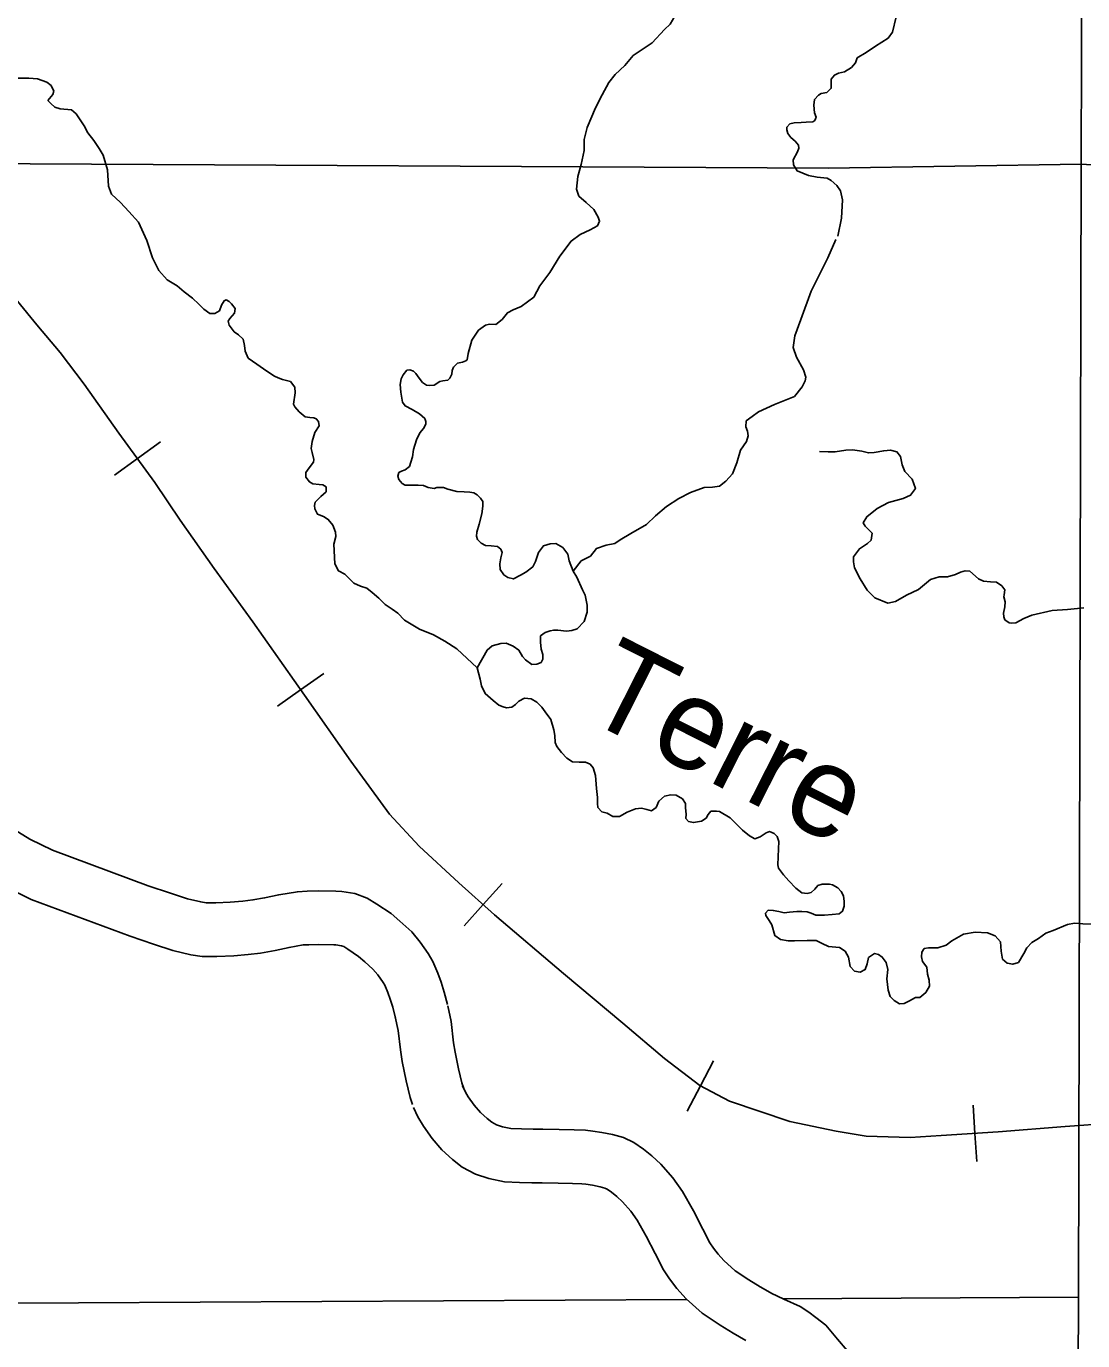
# Model space of a CAD drawing. Extents: x 8749 to 11879, y 13275 to 15339.
# Drawn here: x 10219.7 to 10318.2, y 14295 to 14417.5 of the extents above; entities that cross this region are included whole.
import ezdxf

# ---------------------------------------------------------------- set-up
doc = ezdxf.new("R2010")
doc.units = 0
for name, color, linetype in [('Level 10', 7, 'Continuous'), ('Level 31', 7, 'Continuous'), ('Level 35', 7, 'Continuous'), ('Level 4', 7, 'Continuous'), ('Level 40', 7, 'Continuous'), ('Level 5', 7, 'Continuous')]:
    doc.layers.add(name, color=color, linetype=linetype)

msp = doc.modelspace()

# ---------------------------------------------------------------- linework, layer by layer
at = {"layer": 'Level 10'}
for points in [[(10258.95, 14326.33), (10258.65, 14327.48), (10258.35, 14328.41), (10258.06, 14329.25), (10257.59, 14330.35), (10257.16, 14331.1), (10256.41, 14332.15), (10255.62, 14333.12), (10254.51, 14334.1), (10253.68, 14334.81), (10252.37, 14335.69), (10251.46, 14336.26), (10250.3, 14336.67), (10249.08, 14336.86), (10248.54, 14336.89), (10246.89, 14336.92), (10245.85, 14336.9), (10244.95, 14336.85), (10243.21, 14336.56), (10241.89, 14336.27), (10240.8, 14336.08), (10239.85, 14335.97), (10238.69, 14335.87), (10237.34, 14335.81), (10236.45, 14335.82), (10235.94, 14335.89), (10234.71, 14336.18), (10233.11, 14336.71), (10231.02, 14337.41), (10222.1, 14340.72), (10220.01, 14341.74), (10218.54, 14342.64)], [(10217.6, 14337.35), (10220.12, 14336.12), (10229.36, 14332.69), (10231.53, 14331.96), (10233.34, 14331.37), (10235.02, 14330.97), (10236.07, 14330.82), (10237.43, 14330.8), (10239.02, 14330.88), (10240.35, 14330.99), (10241.52, 14331.12), (10242.87, 14331.36), (10244.17, 14331.65), (10245.5, 14331.88), (10246.03, 14331.91), (10246.89, 14331.92), (10248.35, 14331.89), (10248.55, 14331.88), (10249.07, 14331.8), (10249.28, 14331.73), (10249.65, 14331.49), (10250.65, 14330.82), (10251.23, 14330.32), (10252, 14329.64), (10252.44, 14329.11), (10252.95, 14328.39), (10253.11, 14328.12), (10253.39, 14327.46), (10253.61, 14326.82), (10253.84, 14326.09), (10254.11, 14325.07)], [(10260.47, 14318.49), (10260.3, 14319.03), (10259.97, 14320.33), (10259.66, 14321.88), (10259.52, 14322.77), (10259.29, 14324.74), (10258.97, 14326.22)], [(10254.08, 14325.18), (10254.35, 14323.92), (10254.57, 14322.11), (10254.73, 14321.02), (10255.09, 14319.22), (10255.48, 14317.67), (10255.69, 14317.01)], [(10289.27, 14299.36), (10288.12, 14300.02), (10287.05, 14300.66), (10285.79, 14301.51), (10284.72, 14302.47), (10284.18, 14303.05), (10283.76, 14303.62), (10283.43, 14304.12), (10282.77, 14305.4), (10281.89, 14307.1), (10280.88, 14308.91), (10279.96, 14310.18), (10278.86, 14311.44), (10278.02, 14312.21), (10277.24, 14312.85), (10276.34, 14313.47), (10275.36, 14313.92), (10274.35, 14314.21), (10273.33, 14314.41), (10272.51, 14314.53), (10271.83, 14314.61), (10270.75, 14314.64), (10269.36, 14314.68), (10267.83, 14314.7), (10266.95, 14314.71), (10265.85, 14314.75), (10264.84, 14314.78), (10264.07, 14314.94), (10263.52, 14315.12), (10263.08, 14315.35), (10262.66, 14315.69), (10262.03, 14316.27), (10261.45, 14316.95), (10260.89, 14317.72), (10260.63, 14318.16), (10260.36, 14318.76)], [(10255.79, 14316.73), (10256.18, 14315.86), (10256.7, 14314.98), (10257.51, 14313.85), (10258.43, 14312.79), (10259.4, 14311.89), (10260.32, 14311.16), (10261.55, 14310.5), (10262.79, 14310.1), (10264.25, 14309.8), (10265.67, 14309.75), (10266.82, 14309.71), (10267.77, 14309.7), (10269.26, 14309.68), (10270.61, 14309.64), (10271.47, 14309.62), (10271.85, 14309.57), (10272.47, 14309.48), (10273.19, 14309.34), (10273.62, 14309.22), (10273.85, 14309.11), (10274.24, 14308.84), (10274.74, 14308.43), (10275.27, 14307.95), (10276.04, 14307.06), (10276.65, 14306.22), (10277.49, 14304.73), (10278.32, 14303.11), (10279.1, 14301.59), (10279.66, 14300.75), (10280.34, 14299.84), (10281.21, 14298.9), (10282.7, 14297.56), (10284.37, 14296.43), (10285.6, 14295.7), (10286.78, 14295.02)], [(10312.08, 14282.71), (10310.54, 14283.26), (10308.6, 14283.94), (10306.58, 14284.69), (10305.32, 14285.26), (10304.22, 14285.88), (10302.91, 14286.64), (10301.87, 14287.33), (10301.09, 14287.96), (10300.3, 14288.72), (10299.53, 14289.59), (10298.53, 14290.84), (10297.57, 14292.12), (10296.97, 14293.05), (10296.21, 14294.07), (10295.33, 14295.14), (10294.22, 14296.43), (10293.3, 14297.15), (10292.66, 14297.65), (10291.83, 14298.17), (10290.31, 14298.85), (10289.13, 14299.43)]]:
    msp.add_lwpolyline(points, dxfattribs=at)
at = {"layer": 'Level 31'}
for points in [[(10210.39, 14399.97), (10213.55, 14397.31), (10216.16, 14394.92), (10218.86, 14391.9), (10220.65, 14389.69), (10222.82, 14387.12), (10225.07, 14384.16), (10228.31, 14379.61), (10231.64, 14375.01), (10234.03, 14371.49), (10237.18, 14366.99), (10240.78, 14362.01), (10245.6, 14355.16), (10249.93, 14349.03), (10253.53, 14344.07), (10256.32, 14341.1), (10260.01, 14337.67), (10263.33, 14334.69)], [(10263.33, 14334.69), (10269.77, 14329.23), (10275.31, 14324.59), (10279.18, 14321.3), (10282.47, 14318.78), (10285.25, 14317.31), (10290.88, 14315.42), (10295.21, 14314.52), (10298, 14314.06), (10302.1, 14313.93), (10304.98, 14314.11), (10310.29, 14314.47), (10316.55, 14314.97), (10320.86, 14315.28)]]:
    msp.add_lwpolyline(points, dxfattribs=at)
at = {"layer": 'Level 35'}
for points in [[(10276.27, 14414.82), (10278.04, 14415.99), (10279.19, 14417.24), (10279.71, 14417.73), (10280.15, 14418.47), (10280.03, 14419.36), (10279.76, 14420.39), (10279.54, 14422.04), (10280.08, 14423.37), (10281.01, 14424.3), (10281.55, 14424.42), (10281.89, 14424.89), (10282.04, 14425.48), (10281.97, 14426.54), (10282.02, 14427.15), (10281.82, 14428.01)], [(10297.15, 14414.58), (10298, 14415.1), (10298.86, 14415.67), (10300.06, 14416.43), (10300.45, 14416.99), (10300.8, 14418.42), (10300.8, 14419.75), (10300.82, 14420.78), (10301.16, 14421.25), (10301.73, 14421.64), (10302.25, 14422.11), (10302.3, 14422.67), (10302.32, 14422.99), (10302.52, 14423.36), (10302.81, 14423.63), (10303.16, 14423.71), (10304.06, 14423.46), (10304.95, 14423.41), (10306.47, 14423.56), (10307.14, 14423.88)], [(10271.2, 14401.7), (10270.99, 14402.35), (10271.11, 14403.53), (10271.43, 14404.66), (10271.7, 14405.96), (10271.68, 14406.97), (10271.97, 14408.08), (10272.76, 14409.92), (10273.37, 14411.15), (10273.99, 14412.28), (10274.6, 14413.05), (10275.49, 14413.86), (10276.27, 14414.82)], [(10291.19, 14405.07), (10291.6, 14405.83), (10291.7, 14406.17), (10291.67, 14406.44), (10291.38, 14406.81), (10290.98, 14407.16), (10290.69, 14407.53), (10290.59, 14407.89), (10290.61, 14408.12), (10290.89, 14408.44), (10291.28, 14408.53), (10291.94, 14408.56), (10292.41, 14408.58), (10293.02, 14408.61), (10293.22, 14408.76), (10293.32, 14409.05), (10293.19, 14409.47), (10293.12, 14410.18), (10293.17, 14410.7), (10293.54, 14411.12), (10293.81, 14411.26), (10294.32, 14411.36), (10294.74, 14411.76), (10294.74, 14412.22), (10294.72, 14412.59), (10295.04, 14412.98), (10295.43, 14413.16), (10295.97, 14413.28), (10296.63, 14413.7), (10297, 14414.12), (10297.15, 14414.58)], [(10221.68, 14410.61), (10222.15, 14411.17), (10222.22, 14411.49), (10222, 14412), (10221.58, 14412.32), (10220.72, 14412.62), (10219.91, 14412.69), (10218.76, 14412.69), (10217.6, 14412.5), (10216.32, 14412.1), (10215.59, 14411.86), (10214.95, 14411.88), (10214.55, 14412.3), (10214.53, 14412.82)], [(10226.84, 14405.51), (10226.45, 14406.14), (10225.98, 14406.87), (10225.39, 14407.59), (10225.07, 14408.25), (10224.31, 14409.36), (10223.87, 14409.73), (10222.83, 14409.85), (10222.32, 14410), (10221.97, 14410.32), (10221.68, 14410.61)], [(10231.43, 14395.93), (10230.92, 14397.57), (10230.13, 14399.26), (10229.22, 14400.27), (10228.44, 14401.11), (10227.6, 14401.89), (10227.33, 14402.63), (10227.23, 14404.16), (10226.84, 14405.51)], [(10295.36, 14397.95), (10295.68, 14399.64), (10295.8, 14401.34), (10295.6, 14402.18), (10295.26, 14402.69), (10294.74, 14403.16), (10294.35, 14403.38), (10293.44, 14403.46), (10292.63, 14403.63), (10291.57, 14404.05), (10291.23, 14404.61), (10291.19, 14405.07)], [(10260.87, 14387.01), (10261.21, 14388.26), (10261.85, 14389.19), (10262.49, 14389.68), (10262.88, 14389.76), (10263.47, 14389.73), (10264.06, 14390.2), (10264.53, 14390.82), (10265.07, 14391.09), (10265.83, 14391.41), (10266.99, 14392.29), (10267.55, 14393.32), (10268.48, 14394.58), (10269.44, 14396.1), (10270.47, 14397.5), (10271.33, 14398.12), (10272.24, 14398.54), (10272.93, 14398.93), (10273.13, 14399.35), (10273.01, 14399.74), (10272.59, 14400.46), (10271.88, 14401.09), (10271.2, 14401.7)], [(10292.16, 14385.49), (10291.5, 14386.68), (10291.18, 14387.59), (10291.33, 14388.67), (10291.89, 14390.19), (10292.85, 14392.85), (10294.42, 14395.95), (10295.18, 14397.64)], [(10239.04, 14389.03), (10238.6, 14389.66), (10238.5, 14390.05), (10238.65, 14390.3), (10239.09, 14390.79), (10239.14, 14391.21), (10238.8, 14391.65), (10238.6, 14391.87), (10238.31, 14392.02), (10238.11, 14391.94), (10237.87, 14391.53), (10237.67, 14391.01), (10237.25, 14390.76), (10236.78, 14390.76), (10236.22, 14391.16), (10235.75, 14391.62), (10235.16, 14392.19), (10234.38, 14392.76), (10233.74, 14393.32), (10232.8, 14393.89), (10232.04, 14394.77), (10231.43, 14395.93)], [(10244.6, 14382.31), (10244.74, 14383.35), (10244.7, 14383.89), (10244.3, 14384.4), (10243.57, 14384.6), (10243.15, 14384.75), (10242.8, 14384.92), (10242.09, 14385.39), (10241.18, 14386.03), (10240.37, 14386.59), (10240.08, 14387.23), (10240.03, 14387.77), (10239.88, 14388.36), (10239.46, 14388.78), (10239.04, 14389.03)], [(10254.81, 14385.05), (10255.16, 14385.47), (10255.45, 14385.51), (10255.77, 14385.37), (10255.99, 14385.17), (10256.3, 14384.71), (10256.62, 14384.33), (10256.98, 14384.06), (10257.28, 14384.03), (10257.69, 14384.08), (10258.22, 14384.4), (10258.52, 14384.49), (10258.97, 14384.55), (10259.18, 14384.72), (10259.34, 14385.11), (10259.37, 14385.43), (10259.52, 14385.76), (10259.89, 14386.12), (10260.34, 14386.21), (10260.67, 14386.33), (10260.79, 14386.44), (10260.87, 14387.01)], [(10282.88, 14374.53), (10283.66, 14374.57), (10284.33, 14374.67), (10284.91, 14375.11), (10285.53, 14375.82), (10285.92, 14376.83), (10286.27, 14378.01), (10286.83, 14378.82), (10287, 14379.36), (10286.93, 14379.78), (10286.78, 14380.2), (10286.81, 14380.74), (10287.37, 14381.16), (10287.94, 14381.6), (10289.46, 14382.26), (10291.3, 14383.03), (10292.02, 14383.91), (10292.31, 14384.48), (10292.36, 14384.82), (10292.16, 14385.49)], [(10255.77, 14378.08), (10256.06, 14378.97), (10256.36, 14379.62), (10256.71, 14380.04), (10256.94, 14380.43), (10256.94, 14380.7), (10256.82, 14380.96), (10256.34, 14381.41), (10255.64, 14381.8), (10254.99, 14382.14), (10254.75, 14382.5), (10254.66, 14383.05), (10254.61, 14383.43), (10254.52, 14384.15), (10254.62, 14384.66), (10254.81, 14385.05)], [(10248.36, 14369.26), (10248.55, 14369.96), (10248.5, 14370.38), (10248.26, 14371.02), (10247.82, 14371.56), (10247.37, 14371.83), (10246.81, 14372.05), (10246.59, 14372.54), (10246.56, 14372.86), (10246.61, 14373.18), (10247.13, 14373.7), (10247.64, 14374.14), (10247.62, 14374.58), (10247.32, 14374.78), (10246.98, 14374.81), (10246.39, 14374.88), (10246.07, 14375.05), (10245.75, 14375.49), (10245.73, 14375.94), (10246.05, 14376.38), (10246.46, 14376.9), (10246.49, 14377.14), (10246.34, 14377.78), (10246.24, 14378.17), (10246.34, 14378.81), (10246.59, 14379.67), (10246.98, 14380.29), (10246.91, 14380.68), (10246.71, 14380.93), (10246.49, 14381.03), (10246.12, 14381.05), (10245.68, 14381.13), (10245.11, 14381.59), (10244.72, 14382.06), (10244.6, 14382.31)], [(10261.9, 14371.1), (10262.16, 14372.08), (10262.23, 14372.78), (10262.25, 14373.23), (10262.04, 14373.55), (10261.73, 14373.85), (10261.42, 14374.04), (10261.03, 14374.09), (10260.5, 14374.12), (10259.81, 14374.15), (10258.97, 14374.37), (10258.59, 14374.52), (10257.95, 14374.52), (10257.69, 14374.44), (10257.15, 14374.52), (10256.71, 14374.71), (10256.22, 14374.75), (10255.76, 14374.75), (10255.01, 14374.76), (10254.72, 14374.91), (10254.42, 14375.27), (10254.32, 14375.59), (10254.42, 14375.92), (10254.67, 14376.05), (10255.01, 14376.18), (10255.4, 14376.5), (10255.54, 14376.9), (10255.69, 14377.39), (10255.77, 14378.08)], [(10300.03, 14363.75), (10298.8, 14364.25), (10298.1, 14364.95), (10297.42, 14366.03), (10296.9, 14367.03), (10296.8, 14367.61), (10296.82, 14368.06), (10297.37, 14368.82), (10298.13, 14369.32), (10298.45, 14369.62), (10298.55, 14370.27), (10297.9, 14370.93), (10297.7, 14371.25), (10298.05, 14371.8), (10299.03, 14372.56), (10300.08, 14373.14), (10301.44, 14373.51), (10302.14, 14373.81), (10302.59, 14374.44), (10302.27, 14375.32), (10301.61, 14376.02), (10301.34, 14376.65), (10301.21, 14377.43), (10300.86, 14377.86), (10300.26, 14378.01), (10299.63, 14377.96), (10298.73, 14377.78), (10298.2, 14377.76), (10297.6, 14377.91), (10296.72, 14378.03), (10296.09, 14378.01), (10295.09, 14377.86), (10294.46, 14377.86), (10293.63, 14377.88)], [(10270.67, 14366.72), (10271.43, 14367.7), (10272.27, 14368.14), (10272.83, 14368.85), (10273.74, 14369.17), (10274.55, 14369.32), (10275.05, 14369.64), (10276.05, 14370.23), (10277.5, 14371.09), (10278.34, 14371.9), (10279.37, 14372.76), (10280.52, 14373.52), (10281.61, 14374.07), (10282.88, 14374.53)], [(10270.67, 14366.72), (10270.3, 14367.68), (10270.16, 14368.32), (10269.69, 14368.93), (10269.05, 14369.3), (10268.53, 14369.28), (10267.9, 14369.08), (10267.45, 14368.47), (10267.16, 14367.63), (10266.91, 14367.14), (10266.27, 14366.65), (10265.76, 14366.35), (10265.1, 14366.01), (10264.58, 14366.13), (10264.21, 14366.38), (10263.87, 14366.89), (10263.84, 14367.43), (10263.92, 14367.97), (10264.06, 14368.47), (10263.92, 14368.79), (10263.62, 14369.03), (10263.01, 14369.1), (10262.49, 14369.13), (10262.1, 14369.33), (10261.75, 14369.69), (10261.66, 14369.99), (10261.7, 14370.38), (10261.9, 14371.1)], [(10250.21, 14365.61), (10249.36, 14366.45), (10248.77, 14366.75), (10248.45, 14367.41), (10248.36, 14369.26)], [(10271.98, 14363.57), (10271.8, 14364.48), (10271.53, 14365), (10271.02, 14366.18), (10270.67, 14366.72)], [(10308.48, 14366.01), (10307.66, 14366.74), (10307.23, 14366.76), (10306.78, 14366.64), (10306.33, 14366.41), (10305.57, 14366.19), (10304.79, 14366.19), (10303.99, 14365.94), (10302.89, 14365.01), (10301.76, 14364.48), (10300.73, 14363.9), (10300.03, 14363.75)], [(10312.69, 14362.33), (10311.95, 14361.9), (10311.59, 14361.88), (10311.32, 14361.93), (10310.94, 14362.21), (10310.82, 14362.48), (10310.79, 14362.83), (10310.92, 14363.41), (10310.97, 14363.86), (10310.84, 14364.34), (10310.87, 14364.54), (10310.94, 14364.99), (10310.64, 14365.37), (10310.16, 14365.72), (10309.59, 14365.75), (10308.93, 14365.8), (10308.48, 14366.01)], [(10261.73, 14357.71), (10259.82, 14359.49), (10258.69, 14360.2), (10257.63, 14360.79), (10256.35, 14361.31), (10254.93, 14362.15), (10254.31, 14362.83), (10253.8, 14363.18), (10253.13, 14363.62), (10252.55, 14364.21), (10251.91, 14364.75), (10251.44, 14365.15), (10250.85, 14365.32), (10250.21, 14365.61)], [(10261.73, 14357.71), (10262.64, 14359.37), (10263.11, 14359.78), (10263.92, 14359.98), (10264.41, 14360.01), (10265.08, 14359.74), (10265.59, 14359.37), (10265.94, 14358.78), (10266.21, 14358.48), (10266.8, 14358.04), (10267.29, 14358.06), (10267.68, 14358.21), (10267.83, 14358.53), (10267.83, 14358.97), (10267.68, 14359.46), (10267.61, 14360.1), (10267.63, 14360.69), (10268.07, 14361.01), (10268.52, 14361.16), (10268.86, 14361.24), (10269.25, 14361.24), (10270.06, 14361.14), (10270.53, 14361.19), (10271.05, 14361.36), (10271.68, 14362.05), (10271.98, 14362.91), (10271.98, 14363.57)], [(10318.31, 14363.31), (10317.71, 14363.26), (10316.78, 14363.16), (10315.35, 14363.08), (10313.45, 14362.63), (10312.69, 14362.33)], [(10268.98, 14350.75), (10268.96, 14351.41), (10268.88, 14351.93), (10268.59, 14352.89), (10268.05, 14353.62), (10267.75, 14354.04), (10267.29, 14354.53), (10266.75, 14354.83), (10266.13, 14354.9), (10265.59, 14354.61), (10265.3, 14354.31), (10264.95, 14354.04), (10264.44, 14353.99), (10264.14, 14354.07), (10263.75, 14354.24), (10263.21, 14354.68), (10262.47, 14355.32), (10262.13, 14356.03), (10261.98, 14356.65), (10261.73, 14357.71)], [(10278.4, 14344.69), (10277.99, 14344.38), (10277.53, 14344.51), (10277.04, 14344.63), (10276.47, 14344.58), (10275.71, 14344.26), (10275, 14343.87), (10274.36, 14343.87), (10273.84, 14344.16), (10273.35, 14344.31), (10272.98, 14344.7), (10272.93, 14345.07), (10272.93, 14345.64), (10272.86, 14346.47), (10272.74, 14347.68), (10272.54, 14348.39), (10272.24, 14348.74), (10271.83, 14348.91), (10271.24, 14348.93), (10270.6, 14348.96), (10270.08, 14349.3), (10269.57, 14349.84), (10269.15, 14350.39), (10268.98, 14350.75)], [(10289.75, 14339.36), (10289.83, 14340.85), (10289.85, 14341.54), (10289.68, 14341.98), (10289.41, 14342.28), (10288.99, 14342.45), (10288.67, 14342.35), (10288.11, 14341.96), (10287.62, 14341.79), (10287.1, 14342.06), (10286.46, 14342.6), (10285.8, 14343.24), (10285.31, 14343.75), (10284.33, 14344.32), (10284.03, 14344.35), (10283.51, 14344.37), (10283.27, 14344.05), (10283.07, 14343.71), (10282.63, 14343.44), (10281.89, 14343.29), (10281.43, 14343.39), (10281.18, 14343.68), (10281.21, 14344.07), (10281.16, 14344.66), (10281.13, 14345.06), (10280.86, 14345.5), (10280.27, 14345.85), (10279.78, 14345.89), (10279.19, 14345.75), (10278.67, 14345.28), (10278.4, 14344.69)], [(10299.92, 14328.74), (10300, 14329.58), (10299.87, 14330.26), (10299.5, 14330.76), (10299.16, 14331), (10298.77, 14331.08), (10298.2, 14330.71), (10298.08, 14330.12), (10297.91, 14329.58), (10297.44, 14329.35), (10296.92, 14329.43), (10296.51, 14329.87), (10296.36, 14330.73), (10296.04, 14331.3), (10295.52, 14331.64), (10294.49, 14331.74), (10293.88, 14332.01), (10293.34, 14332.3), (10292.48, 14332.3), (10291.32, 14332.28), (10290.71, 14332.28), (10290, 14332.38), (10289.48, 14332.75), (10289.21, 14333.76), (10288.96, 14334.15), (10288.64, 14334.62), (10288.62, 14334.86), (10288.87, 14335.13), (10289.33, 14335.11), (10289.85, 14334.99), (10290.34, 14334.89), (10290.83, 14334.94), (10291.54, 14334.99), (10291.99, 14335.01), (10292.5, 14334.96), (10292.87, 14334.86), (10293.31, 14334.67), (10294.1, 14334.67), (10294.81, 14334.71), (10295.48, 14334.79), (10295.79, 14335.03), (10295.94, 14335.5), (10295.94, 14335.92), (10295.89, 14336.46), (10295.67, 14336.88), (10295.35, 14337.2), (10294.86, 14337.49), (10294.57, 14337.54), (10293.9, 14337.54), (10293.49, 14337.42), (10293.21, 14337.1), (10292.87, 14336.78), (10292.48, 14336.68), (10291.99, 14336.73), (10291.45, 14337.17), (10290.78, 14337.86), (10290.27, 14338.43), (10289.83, 14339.03), (10289.75, 14339.36)], [(10326.61, 14332.38), (10326.55, 14332.94), (10326.52, 14333.24), (10326.15, 14333.61), (10325.49, 14333.98), (10324.92, 14334.49), (10324.26, 14335.18), (10323.99, 14335.62), (10323.89, 14336.24), (10323.67, 14336.68), (10323.35, 14336.98), (10322.88, 14337), (10322.29, 14336.93), (10321.78, 14336.56), (10321.24, 14335.92), (10321.04, 14335.06), (10320.72, 14334.37), (10320.35, 14334.05), (10319.76, 14333.88), (10319.13, 14333.83), (10318.19, 14333.85), (10317.43, 14333.93), (10316.77, 14333.78)], [(10316.77, 14333.78), (10315.42, 14333.24), (10314.76, 14332.97), (10314.07, 14332.48), (10313.45, 14332.11), (10312.99, 14331.62), (10312.69, 14331.08), (10312.2, 14330.26), (10311.66, 14330.09), (10311.15, 14330.19), (10310.7, 14330.56), (10310.6, 14331.3), (10310.51, 14332.16), (10310.04, 14332.72), (10309.3, 14333.02), (10308.15, 14333.07), (10307.07, 14332.9), (10305.99, 14332.28), (10305.45, 14331.86), (10304.68, 14331.62), (10303.82, 14331.62), (10303.41, 14331.54), (10303.18, 14331.22), (10303.16, 14330.78), (10303.26, 14330.34), (10303.65, 14329.8), (10303.73, 14329.16), (10303.87, 14328.59), (10303.9, 14328.05), (10303.55, 14327.44), (10303.01, 14326.99), (10302.6, 14326.97), (10302.05, 14326.67), (10301.54, 14326.43), (10301.1, 14326.38), (10300.61, 14326.7), (10300.24, 14327.09), (10300.06, 14327.66), (10299.92, 14328.74)]]:
    msp.add_lwpolyline(points, dxfattribs=at)
at = {"layer": 'Level 4'}
msp.add_lwpolyline([(10318.19, 14456.3), (10318.04, 14404.67), (10317.79, 14299.04), (10317.77, 14292.07), (10317.72, 14280.03)], dxfattribs=at)
at = {"layer": 'Level 40'}
for p, q in [((10230.03, 14377.23), (10232.17, 14378.78)), ((10230.03, 14377.23), (10227.89, 14375.68)), ((10245.25, 14355.66), (10247.41, 14357.18)), ((10245.25, 14355.66), (10243.09, 14354.14)), ((10262.27, 14335.64), (10264.04, 14337.6)), ((10262.27, 14335.64), (10260.51, 14333.68)), ((10282.54, 14318.74), (10283.77, 14321.07)), ((10282.54, 14318.74), (10281.31, 14316.4)), ((10308.14, 14314.32), (10307.96, 14316.96)), ((10308.14, 14314.32), (10308.32, 14311.69))]:
    msp.add_line(p, q, dxfattribs=at)
msp.add_lwpolyline([(10218.86, 14391.9), (10220.65, 14389.69), (10222.82, 14387.12), (10225.07, 14384.16), (10228.31, 14379.61), (10231.64, 14375.01), (10234.03, 14371.49), (10237.18, 14366.99), (10240.78, 14362.01), (10245.6, 14355.16), (10249.93, 14349.03), (10253.53, 14344.07), (10256.32, 14341.1), (10260.01, 14337.67), (10263.33, 14334.69), (10269.77, 14329.23), (10275.31, 14324.59), (10279.18, 14321.3), (10282.47, 14318.78), (10285.25, 14317.31), (10290.88, 14315.42), (10295.21, 14314.52), (10298, 14314.06), (10302.1, 14313.93), (10304.98, 14314.11), (10310.29, 14314.47), (10316.55, 14314.97), (10320.86, 14315.28)], dxfattribs=at)
at = {"layer": 'Level 5'}
for points in [[(10214.27, 14404.75), (10294.48, 14404.3), (10318.04, 14404.67)], [(10318.04, 14404.67), (10366.8, 14401.56)], [(10213.15, 14298.47), (10281.27, 14298.84)], [(10290.22, 14298.89), (10317.79, 14299.04)]]:
    msp.add_lwpolyline(points, dxfattribs=at)

# ---------------------------------------------------------------- texts
at = {"layer": 'Level 35'}
msp.add_text('Terre', height=8.448, rotation=333.1312, dxfattribs=at).set_placement((10271.27, 14353.22))

doc.saveas('drawing.dxf')
